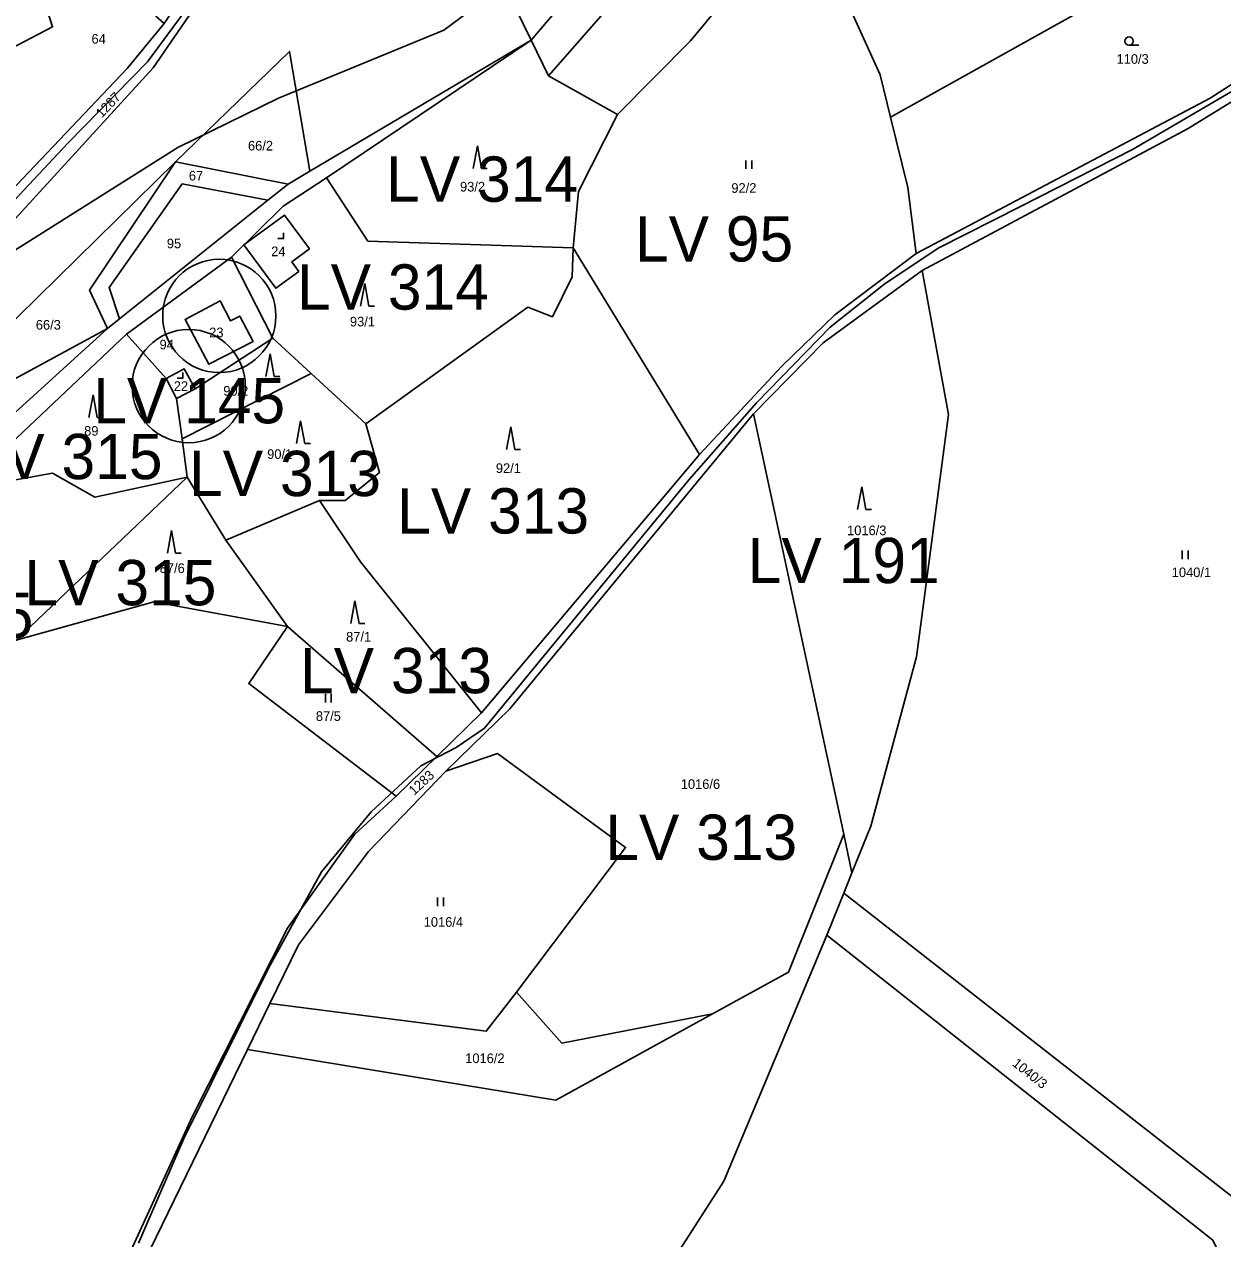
# Model space of a CAD drawing. Extents: x -588699 to -585793, y -1060280 to -1056731.
# Drawn here: x -588254.6 to -588042.9, y -1058596 to -1058381.5 of the extents above; entities that cross this region are included whole.
import ezdxf

# ---------------------------------------------------------------- set-up
doc = ezdxf.new("R2010")
doc.units = 0
for name, color, linetype in [('Druh pozemku', 7, 'Continuous'), ('Parcela nároku', 7, 'Continuous'), ('Stavby', 7, 'Continuous'), ('Vnitřní obvod', 7, 'Continuous'), ('Vnější obvod_k šeření', 7, 'Continuous'), ('Vnější obvod_převzatý', 7, 'Continuous')]:
    doc.layers.add(name, color=color, linetype=linetype)

msp = doc.modelspace()

# ---------------------------------------------------------------- linework, layer by layer
at = {"layer": 'Druh pozemku'}
for p, q in [((-588057.71, -1058385.25), (-588059.46, -1058385.25)), ((-588174.55, -1058403.01), (-588175.29, -1058407.01)), ((-588174.55, -1058403.01), (-588173.82, -1058407.01)), ((-588127.14, -1058405.59), (-588127.14, -1058407.09)), ((-588126.11, -1058407.09), (-588126.11, -1058405.59)), ((-588173.82, -1058407.01), (-588172.82, -1058407.01)), ((-588194.48, -1058427.33), (-588195.21, -1058431.33)), ((-588194.48, -1058427.33), (-588193.75, -1058431.33)), ((-588193.75, -1058431.33), (-588192.75, -1058431.33)), ((-588211.17, -1058439.75), (-588211.91, -1058443.75)), ((-588211.17, -1058439.75), (-588210.44, -1058443.75)), ((-588210.44, -1058443.75), (-588209.44, -1058443.75)), ((-588242.46, -1058446.99), (-588243.2, -1058450.99)), ((-588242.46, -1058446.99), (-588241.73, -1058450.99)), ((-588241.73, -1058450.99), (-588240.73, -1058450.99)), ((-588205.79, -1058451.56), (-588206.53, -1058455.56)), ((-588205.79, -1058451.56), (-588205.06, -1058455.56)), ((-588168.68, -1058452.6), (-588169.42, -1058456.6)), ((-588168.68, -1058452.6), (-588167.95, -1058456.6)), ((-588205.06, -1058455.56), (-588204.06, -1058455.56)), ((-588167.95, -1058456.6), (-588166.95, -1058456.6)), ((-588106.67, -1058463.21), (-588107.41, -1058467.21)), ((-588106.67, -1058463.21), (-588105.94, -1058467.21)), ((-588105.94, -1058467.21), (-588104.94, -1058467.21)), ((-588228.6, -1058470.93), (-588229.33, -1058474.93)), ((-588228.6, -1058470.93), (-588227.87, -1058474.93)), ((-588227.87, -1058474.93), (-588226.87, -1058474.93)), ((-588050.06, -1058474.47), (-588050.06, -1058475.97)), ((-588049.04, -1058475.97), (-588049.04, -1058474.47)), ((-588196.21, -1058483.32), (-588196.95, -1058487.32)), ((-588196.21, -1058483.32), (-588195.48, -1058487.32)), ((-588195.48, -1058487.32), (-588194.48, -1058487.32)), ((-588201.41, -1058499.77), (-588201.41, -1058501.27)), ((-588200.39, -1058501.27), (-588200.39, -1058499.77)), ((-588181.6, -1058535.74), (-588181.6, -1058537.24)), ((-588180.58, -1058537.24), (-588180.58, -1058535.74))]:
    msp.add_line(p, q, dxfattribs=at)
for points in [[(-588209.81, -1058419.39), (-588208.81, -1058419.39), (-588208.81, -1058418.39)], [(-588227.61, -1058444.03), (-588226.61, -1058444.03), (-588226.61, -1058443.03)]]:
    msp.add_lwpolyline(points, dxfattribs=at)
msp.add_circle((-588059.46, -1058384.5), 0.75, dxfattribs=at)
at = {"layer": 'Parcela nároku'}
for points in [[(-588283.37, -1058455.17), (-588274.9, -1058429.78), (-588264.76, -1058419.13), (-588236.43, -1058389.38), (-588229.89, -1058381.41), (-588202.03, -1058340), (-588202.09, -1058337.86), (-588202.2, -1058334.18), (-588202.91, -1058310.84), (-588201.43, -1058292.5), (-588195.18, -1058273.49), (-588188.82, -1058270.29), (-588198.66, -1058291.81), (-588199.76, -1058311.5), (-588198.93, -1058333.77), (-588198.84, -1058336.33), (-588199.24, -1058341.78), (-588231.84, -1058389.25), (-588271.28, -1058432.34), (-588280.04, -1058457.03), (-588290.75, -1058481.45), (-588298.28, -1058488.56), (-588287.12, -1058463.52)], [(-588161.36, -1058356.04), (-588160.44, -1058364.53), (-588154.15, -1058371.52), (-588165.06, -1058384.36), (-588190.26, -1058332.87), (-588167.4, -1058320.3), (-588157.01, -1058313.06), (-588146.99, -1058325.07)], [(-588080.48, -1058360.43), (-588071.87, -1058356.13), (-588065.25, -1058377.7), (-588101.59, -1058397.94), (-588103.43, -1058390.47), (-588117.02, -1058360.48), (-588091.25, -1058324.55), (-588089.43, -1058322.02), (-588084.22, -1058315.89), (-588074.83, -1058346.49), (-588077.99, -1058347.4)], [(-588165.06, -1058384.36), (-588154.15, -1058371.52), (-588160.44, -1058364.53), (-588161.36, -1058356.04), (-588146.99, -1058325.07), (-588136.79, -1058337.39), (-588149.78, -1058376.65), (-588161.99, -1058390.65)], [(-588199.24, -1058341.78), (-588198.84, -1058336.33), (-588190.26, -1058332.87), (-588165.06, -1058384.36), (-588204.14, -1058407.47), (-588207.77, -1058386.34), (-588227.9, -1058405.85), (-588280.04, -1058457.03), (-588271.28, -1058432.34), (-588231.84, -1058389.25)], [(-588117.02, -1058360.48), (-588136.79, -1058337.39), (-588149.78, -1058376.65), (-588161.99, -1058390.65), (-588149.82, -1058397.49), (-588136.9, -1058384.46)], [(-588252.48, -1058372.92), (-588240.01, -1058365.89), (-588240.63, -1058359.1), (-588234.62, -1058357.27), (-588236.71, -1058349.89), (-588238.08, -1058345.41), (-588222.35, -1058343.56), (-588207.43, -1058340.37), (-588231.36, -1058380.12), (-588229.89, -1058381.41), (-588236.43, -1058389.38), (-588264.76, -1058419.13), (-588272.95, -1058394.2), (-588249.61, -1058381.97)], [(-588240.63, -1058359.1), (-588242.14, -1058359.56), (-588250.36, -1058359.85), (-588260.9, -1058362.71), (-588264.27, -1058349.53), (-588265.17, -1058346), (-588266.58, -1058362.77), (-588272.95, -1058394.2), (-588249.61, -1058381.97), (-588252.48, -1058372.92), (-588240.01, -1058365.89)], [(-588065.25, -1058377.7), (-588020.5, -1058352.76), (-588017.24, -1058356.23), (-588026.95, -1058382.89), (-588045.14, -1058394.57), (-588097.06, -1058422.02), (-588098.53, -1058410.35), (-588101.59, -1058397.94)], [(-588149.82, -1058397.49), (-588136.9, -1058384.46), (-588117.02, -1058360.48), (-588103.43, -1058390.47), (-588101.59, -1058397.94), (-588098.53, -1058410.35), (-588097.06, -1058422.02), (-588111.41, -1058432.85), (-588120.77, -1058441.9), (-588135.35, -1058457.5), (-588157.66, -1058421), (-588156.72, -1058411.08)], [(-588204.14, -1058407.47), (-588165.06, -1058384.36), (-588201.23, -1058408.67), (-588208.9, -1058413.66), (-588218.03, -1058422.64), (-588236.56, -1058436.26), (-588265.64, -1058463.66), (-588286.58, -1058483.4), (-588296.31, -1058492.71), (-588301.9, -1058498.09), (-588324.19, -1058519.78), (-588325.72, -1058517.62), (-588320.32, -1058511.91), (-588298.28, -1058488.56), (-588290.75, -1058481.45), (-588239.93, -1058435.27), (-588237.81, -1058433.58), (-588211.56, -1058412.6), (-588208.02, -1058409.77)], [(-588165.06, -1058384.36), (-588201.23, -1058408.67), (-588193.91, -1058419.82), (-588157.66, -1058421), (-588156.72, -1058411.08), (-588149.82, -1058397.49), (-588161.99, -1058390.65)], [(-588096.98, -1058493.24), (-588105.09, -1058523.12), (-588108.4, -1058531.35), (-588109.84, -1058534.93), (-588036.79, -1058592.04), (-588030.19, -1058568.64), (-588017.25, -1058543.67), (-588011.81, -1058474.47), (-588008.24, -1058447.9), (-588007.26, -1058413.92), (-588019.83, -1058414.9), (-588024.83, -1058386.7), (-588025.09, -1058385.21), (-588049.02, -1058399.97), (-588096, -1058425.03), (-588091.36, -1058450.44)], [(-588207.77, -1058386.34), (-588204.14, -1058407.47), (-588208.02, -1058409.77), (-588227.9, -1058405.85)], [(-588239.93, -1058435.27), (-588243.06, -1058428.5), (-588227.9, -1058405.85), (-588280.04, -1058457.03)], [(-588243.06, -1058428.5), (-588227.9, -1058405.85), (-588208.02, -1058409.77), (-588211.56, -1058412.6), (-588226.7, -1058409.73), (-588239.64, -1058428.03), (-588237.81, -1058433.58), (-588239.93, -1058435.27)], [(-588201.23, -1058408.67), (-588208.9, -1058413.66), (-588218.03, -1058422.64), (-588210.69, -1058436.97), (-588203.94, -1058443.19), (-588194.27, -1058452.1), (-588165.68, -1058431.48), (-588161.32, -1058433.18), (-588157.84, -1058426.14), (-588157.66, -1058421), (-588193.91, -1058419.82)], [(-588239.64, -1058428.03), (-588226.7, -1058409.73), (-588211.56, -1058412.6), (-588237.81, -1058433.58)], [(-588207.37, -1058423.51), (-588206.13, -1058425.18), (-588210.19, -1058428.15), (-588215.81, -1058420.51), (-588208.65, -1058415.24), (-588204.23, -1058421.22)], [(-588204.23, -1058421.22), (-588207.37, -1058423.51), (-588206.13, -1058425.18), (-588210.19, -1058428.15), (-588215.81, -1058420.51), (-588208.65, -1058415.24)], [(-588157.84, -1058426.14), (-588161.32, -1058433.18), (-588165.68, -1058431.48), (-588194.27, -1058452.1), (-588191.85, -1058460.66), (-588197.91, -1058465.6), (-588202.43, -1058465.6), (-588195.21, -1058476.48), (-588173.82, -1058503.14), (-588135.35, -1058457.5), (-588157.66, -1058421)], [(-588218.03, -1058422.64), (-588210.69, -1058436.97), (-588224.44, -1058445.89), (-588226.37, -1058442.35), (-588229.56, -1058444.11), (-588236.56, -1058436.26)], [(-588125.78, -1058450.34), (-588113.5, -1058437.77), (-588096, -1058425.03), (-588091.36, -1058450.44), (-588096.98, -1058493.24), (-588105.09, -1058523.12), (-588108.4, -1058531.35), (-588109.86, -1058524.53)], [(-588220.02, -1058430.39), (-588226.19, -1058433.64), (-588221.99, -1058441.58), (-588214.2, -1058437.54), (-588216.55, -1058433.07), (-588218.15, -1058433.92)], [(-588221.99, -1058441.58), (-588214.2, -1058437.54), (-588216.55, -1058433.07), (-588218.15, -1058433.92), (-588220.02, -1058430.39), (-588226.19, -1058433.64)], [(-588280.04, -1058457.03), (-588290.75, -1058481.45), (-588239.93, -1058435.27)], [(-588226.74, -1058454.71), (-588227.7, -1058447.64), (-588229.56, -1058444.11), (-588236.56, -1058436.26), (-588265.64, -1058463.66), (-588249.61, -1058460.78), (-588242.12, -1058465.06), (-588225.81, -1058461.5)], [(-588224.44, -1058445.89), (-588227.7, -1058447.64), (-588226.74, -1058454.71), (-588203.94, -1058443.19), (-588210.69, -1058436.97)], [(-588226.37, -1058442.35), (-588224.44, -1058445.89), (-588227.7, -1058447.64), (-588229.56, -1058444.11)], [(-588203.94, -1058443.19), (-588194.27, -1058452.1), (-588191.85, -1058460.66), (-588197.91, -1058465.6), (-588202.43, -1058465.6), (-588219.01, -1058472.64), (-588225.81, -1058461.5), (-588226.74, -1058454.71)], [(-588148.39, -1058526.89), (-588167.69, -1058552.46), (-588159.67, -1058561.42), (-588133.04, -1058556.28), (-588119.64, -1058548.89), (-588109.86, -1058524.53), (-588125.78, -1058450.34), (-588168.81, -1058502.43), (-588180.14, -1058513.43), (-588171.03, -1058510.3)], [(-588242.12, -1058465.06), (-588225.81, -1058461.5), (-588256.04, -1058490.3), (-588262.95, -1058496.95), (-588268.59, -1058502.25), (-588286.58, -1058483.4), (-588265.64, -1058463.66), (-588249.61, -1058460.78)], [(-588219.01, -1058472.64), (-588208.11, -1058487.86), (-588231.73, -1058483.49), (-588256.04, -1058490.3), (-588225.81, -1058461.5)], [(-588219.01, -1058472.64), (-588202.43, -1058465.6), (-588195.21, -1058476.48), (-588173.82, -1058503.14), (-588181.71, -1058510.81), (-588208.11, -1058487.86)], [(-588262.95, -1058496.95), (-588256.04, -1058490.3), (-588231.73, -1058483.49), (-588208.11, -1058487.86), (-588214.97, -1058497.94), (-588188.92, -1058517.82), (-588196.26, -1058524.58), (-588208.14, -1058541.13), (-588224.97, -1058574.45), (-588238.98, -1058605.06), (-588251.51, -1058638.95), (-588279.94, -1058644.03), (-588291.86, -1058629.85), (-588300.68, -1058609.7), (-588310.57, -1058569.75), (-588313.12, -1058564.65)], [(-588208.11, -1058487.86), (-588214.97, -1058497.94), (-588188.92, -1058517.82), (-588181.71, -1058510.81)], [(-588193.78, -1058527.59), (-588206.18, -1058544.06), (-588211.24, -1058554.46), (-588172.99, -1058559.35), (-588167.69, -1058552.46), (-588148.39, -1058526.89), (-588171.03, -1058510.3), (-588180.14, -1058513.43)], [(-588160.71, -1058571.53), (-588133.04, -1058556.28), (-588119.64, -1058548.89), (-588109.86, -1058524.53), (-588108.4, -1058531.35), (-588109.84, -1058534.93), (-588112.84, -1058542.38), (-588131.02, -1058585.83), (-588144.44, -1058606.7), (-588168.14, -1058675.06), (-588189.32, -1058742.9), (-588190.21, -1058759.8), (-588191.27, -1058761.91), (-588243.79, -1058719.3), (-588252.4, -1058690.54), (-588254.57, -1058673), (-588247.32, -1058639.55), (-588236.75, -1058606.83), (-588215.17, -1058562.54)], [(-588109.84, -1058534.93), (-588036.79, -1058592.04), (-588040.36, -1058604.95), (-588044.66, -1058596.24), (-588112.84, -1058542.38)], [(-588189.32, -1058742.9), (-588190.21, -1058759.8), (-588172.56, -1058777.54), (-588159.73, -1058806.34), (-588132.18, -1058821.5), (-588109.1, -1058827.66), (-588088.15, -1058840.59), (-588084.85, -1058785.48), (-588068.73, -1058707.6), (-588040.36, -1058604.95), (-588044.66, -1058596.24), (-588112.84, -1058542.38), (-588131.02, -1058585.83), (-588144.44, -1058606.7), (-588168.14, -1058675.06)], [(-588215.17, -1058562.54), (-588211.24, -1058554.46), (-588172.99, -1058559.35), (-588167.69, -1058552.46), (-588159.67, -1058561.42), (-588133.04, -1058556.28), (-588160.71, -1058571.53)]]:
    msp.add_lwpolyline(points, close=True, dxfattribs=at)
for points in [[(-588238.98, -1058605.06), (-588224.97, -1058574.45), (-588208.14, -1058541.13), (-588196.26, -1058524.58), (-588188.92, -1058517.82), (-588181.71, -1058510.81), (-588173.82, -1058503.14), (-588135.35, -1058457.5), (-588120.77, -1058441.9), (-588111.41, -1058432.85), (-588097.06, -1058422.02), (-588045.14, -1058394.57), (-588026.95, -1058382.89)], [(-588025.09, -1058385.21), (-588049.02, -1058399.97), (-588096, -1058425.03), (-588113.5, -1058437.77), (-588125.78, -1058450.34), (-588168.81, -1058502.43), (-588180.14, -1058513.43), (-588193.78, -1058527.59), (-588206.18, -1058544.06), (-588211.24, -1058554.46), (-588215.17, -1058562.54), (-588236.75, -1058606.83)]]:
    msp.add_lwpolyline(points, dxfattribs=at)
at = {"layer": 'Stavby'}
for centre in [(-588220.16, -1058433.04), (-588225.56, -1058445.43)]:
    msp.add_circle(centre, 10, dxfattribs=at)
at = {"layer": 'Vnitřní obvod'}
for points in [[(-588355.85, -1058653.02), (-588371.42, -1058587.04), (-588374.97, -1058567.9), (-588371.96, -1058555.68), (-588358.29, -1058536.95), (-588342.57, -1058523.27), (-588333.89, -1058515.71), (-588326.33, -1058511.51), (-588322.58, -1058500.52), (-588320.21, -1058493.58), (-588316.53, -1058486.73), (-588309.31, -1058480.82), (-588294.1, -1058469.33), (-588287.69, -1058461.37), (-588282.59, -1058455.76), (-588275.67, -1058440.51), (-588271.84, -1058430.25), (-588264.08, -1058420.84), (-588246.91, -1058402.51), (-588232.82, -1058388.18), (-588224.91, -1058377.38)], [(-588034.3, -1058389.32), (-588058.84, -1058403.68), (-588078.65, -1058413.73), (-588093.05, -1058421.04), (-588102.56, -1058427.32), (-588112.24, -1058435.02), (-588125.26, -1058448.37), (-588137.15, -1058461.89), (-588161.07, -1058490.93), (-588173.32, -1058505.8), (-588178.32, -1058509.22), (-588184.54, -1058512.46), (-588193.31, -1058520.57), (-588202.1, -1058531.18), (-588211.53, -1058548.31), (-588226.41, -1058578.26), (-588234.44, -1058596.76)]]:
    msp.add_lwpolyline(points, dxfattribs=at)
at = {"layer": 'Vnější obvod_k šeření'}
msp.add_lwpolyline([(-588171.2, -1058375.64), (-588180.48, -1058382.57), (-588209.7, -1058394.6), (-588227.48, -1058403.3), (-588273.77, -1058432.46), (-588285.6, -1058441.48), (-588293.97, -1058445.02), (-588306.52, -1058452.99), (-588311.03, -1058457.51), (-588322.47, -1058465.16), (-588326.26, -1058469.28), (-588331.16, -1058470.85), (-588336.91, -1058471.5), (-588346.39, -1058479.22), (-588355.87, -1058481.96), (-588358.68, -1058484.51), (-588365.15, -1058487.59), (-588371.76, -1058494.19), (-588385.42, -1058518.38), (-588392.18, -1058527.06), (-588393.47, -1058528.71)], dxfattribs=at)
at = {"layer": 'Vnější obvod_převzatý'}
for p, q in [((-588157.66, -1058421), (-588135.35, -1058457.5)), ((-588226.74, -1058454.71), (-588203.94, -1058443.19))]:
    msp.add_line(p, q, dxfattribs=at)
for points in [[(-588218.03, -1058422.64), (-588208.9, -1058413.66), (-588201.23, -1058408.67), (-588165.06, -1058384.36)], [(-588218.03, -1058422.64), (-588210.69, -1058436.97), (-588203.94, -1058443.19), (-588194.27, -1058452.1), (-588165.68, -1058431.48), (-588161.32, -1058433.18), (-588157.84, -1058426.14), (-588157.66, -1058421), (-588156.72, -1058411.08)], [(-588312.54, -1058543.42), (-588311.91, -1058535.6), (-588296.31, -1058492.71), (-588286.58, -1058483.4), (-588265.64, -1058463.66), (-588236.56, -1058436.26)], [(-588236.56, -1058436.26), (-588229.56, -1058444.11), (-588227.7, -1058447.64), (-588226.74, -1058454.71)], [(-588125.78, -1058450.34), (-588109.86, -1058524.53), (-588108.4, -1058531.35)], [(-588226.74, -1058454.71), (-588225.81, -1058461.5), (-588219.01, -1058472.64), (-588208.11, -1058487.86)]]:
    msp.add_lwpolyline(points, dxfattribs=at)

# ---------------------------------------------------------------- texts
at = {"layer": 'Parcela nároku'}
for s, p in [('64', (-588242.73, -1058384.97)), ('110/3', (-588061.67, -1058388.52)), ('66/2', (-588215.09, -1058403.83)), ('67', (-588225.54, -1058409.13)), ('93/2', (-588177.64, -1058411.07)), ('92/2', (-588129.71, -1058411.3)), ('95', (-588229.42, -1058421.09)), ('24', (-588210.99, -1058422.49)), ('66/3', (-588252.57, -1058435.46)), ('93/1', (-588197.08, -1058434.89)), ('23', (-588221.94, -1058436.8)), ('94', (-588230.71, -1058438.94)), ('22', (-588228.2, -1058446.28)), ('90/2', (-588219.45, -1058447.11)), ('89', (-588244.03, -1058454.18)), ('90/1', (-588211.7, -1058458.28)), ('92/1', (-588171.31, -1058460.77)), ('1016/3', (-588109.27, -1058471.75)), ('87/6', (-588230.68, -1058478.42)), ('1040/1', (-588051.92, -1058479.16)), ('87/1', (-588197.76, -1058490.54)), ('87/5', (-588203.1, -1058504.54)), ('1016/6', (-588138.64, -1058516.55)), ('1016/4', (-588184.05, -1058540.89)), ('1016/2', (-588176.72, -1058564.96))]:
    msp.add_text(s, height=1.7, dxfattribs=at).set_placement(p)
for s, rotation, p in [('1287', 46.4629, (-588240.91, -1058398.18)), ('1283', 42.8625, (-588185.74, -1058517.78)), ('1040/3', 321.59, (-588080.21, -1058565.29))]:
    msp.add_text(s, height=1.7, rotation=rotation, dxfattribs=at).set_placement(p)
at = {"layer": 'Vnější obvod_převzatý'}
for s, p in [('LV 314', (-588190.69, -1058412.88)), ('LV 95', (-588146.74, -1058423.43)), ('LV 314', (-588206.44, -1058431.93)), ('LV 145', (-588242.43, -1058452)), ('LV 315', (-588264.09, -1058461.86)), ('LV 313', (-588225.5, -1058464.85)), ('LV 313', (-588188.74, -1058471.46)), ('LV 191', (-588126.81, -1058480.22)), ('LV 315', (-588254.57, -1058484.13)), ('LV 315', (-588286.92, -1058489.88)), ('LV 313', (-588205.9, -1058499.66)), ('LV 313', (-588151.98, -1058529.08))]:
    msp.add_text(s, height=8, dxfattribs=at).set_placement(p)

doc.saveas('drawing.dxf')
